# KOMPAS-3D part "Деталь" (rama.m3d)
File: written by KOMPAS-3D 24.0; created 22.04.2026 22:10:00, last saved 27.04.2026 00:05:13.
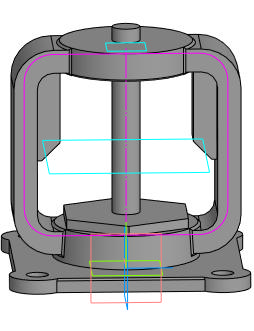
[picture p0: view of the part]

Document properties: Автор: mrdid; Полное имя файла: C:\Работа\ГОТОВЫЕ ИСХОДНИКИ\VSO2130M-F-S Клапан запорный сальниковый DN.ru Ду15-100 Ру40\исходные материалы\DN100\rama.m3d

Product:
- Part/product: Деталь
    Масса: 8.007672

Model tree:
1. Эскиз:2  (with: Ребро.Элемент выдавливания:14)
2. Элемент выдавливания:1
     Расстояние 1 = 10
3. Эскиз:3  (with: Грань.Элемент выдавливания:1, Ребро.Элемент выдавливания:1)
4. Элемент выдавливания:2
     Расстояние 2 = 10
5. Эскиз:4  (with: Грань.Элемент выдавливания:1)
6. Элемент выдавливания:3
     Угол 1 = -3
7. Эскиз:5  (with: Грань.Элемент выдавливания:3, Ребро.Элемент выдавливания:3)
8. Элемент выдавливания:4
9. Эскиз:23  (with: Грань.Элемент выдавливания:4, Ребро.Элемент выдавливания:4)
10. Элемент выдавливания:21  (labels: Деталь2; Грань.Твердое тело1)
     Расстояние 1 = 134.772
11. Эскиз:7  (with: Грань.Элемент выдавливания:4, Ребро.Элемент выдавливания:3)
12. Элемент выдавливания:6  (with: Грань.Элемент выдавливания:3)
     Расстояние 2 = 7
13. Смещенная плоскость:4  (labels: Деталь2; Грань.Твердое тело1)
     Расстояние = 15
14. Эскиз:24  (with: Ребро.Элемент выдавливания:3)
15. Элемент выдавливания:22
     Расстояние 1 = 5; Расстояние 2 = 15
16. Эскиз:25  (with: Ребро.Элемент выдавливания:3)
17. Эскиз:26  (with: Ребро.Элемент выдавливания:3)
18. Элемент по траектории:1
     Длина траектории = 519.209
19. Скругление:8  (with: Ребро.Элемент по траектории:1)
     Радиус = 2
20. Скругление:9  (with: Ребро.Элемент по траектории:1)
     Радиус = 2
21. Смещенная плоскость:5  (with: Грань.Элемент выдавливания:1)
22. Эскиз:27  (with: Вершина.Элемент по траектории:1)
23. Элемент выдавливания:23  (with: Грань.Элемент выдавливания:22)
     Расстояние 1 = 69.5225; Смещение 1 = 5
24. Скругление:1  (with: Ребро.Элемент выдавливания:1)
     Радиус = 1.5
25. Скругление:10  (with: Ребро.Элемент выдавливания:22)
     Радиус = 1
26. Фаска:1  (with: Ребро.Элемент выдавливания:23)
     Угол = 45; Длина 1 = 13; Длина 2 = 13
27. Массив по концентрической сетке:1  (with: Элемент выдавливания:2, Эскиз:3)  (labels: Клапан запорный DN.ru Ду100 Ру40)  (4 pattern instances)
     Шаг 2 = 360

Expressions: DN/2; DN/4; DN/6; H/4-10
Referenced files in C:\Работа\ГОТОВЫЕ ИСХОДНИКИ\VSO2130M-F-S Клапан запорный сальниковый DN.ru Ду15-100 Ру40\исходные материалы\DN100\: VSO2130M-F-S Клапан запорный DN.ru Ду100 Ру40.a3d
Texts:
  DN+5
  Ось Y.Начало координат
